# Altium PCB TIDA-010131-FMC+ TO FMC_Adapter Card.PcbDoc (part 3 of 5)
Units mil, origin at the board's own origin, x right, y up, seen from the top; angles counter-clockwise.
Board outline 2874.02 x 2362.2 mil, 12 copper layers (L1_Top Layer, L2_GND, L3_GND, L4_Signal layer1, L5_GND, L6_Signal Layer2, L7_GND, L8_Signal Layer3, L9_GND, L10_Signal Layer4, L11_GND, L12_Bottom Layer), stack 65.6 mil thick; 64 components, 219 nets, 2252 pads, 791 vias.
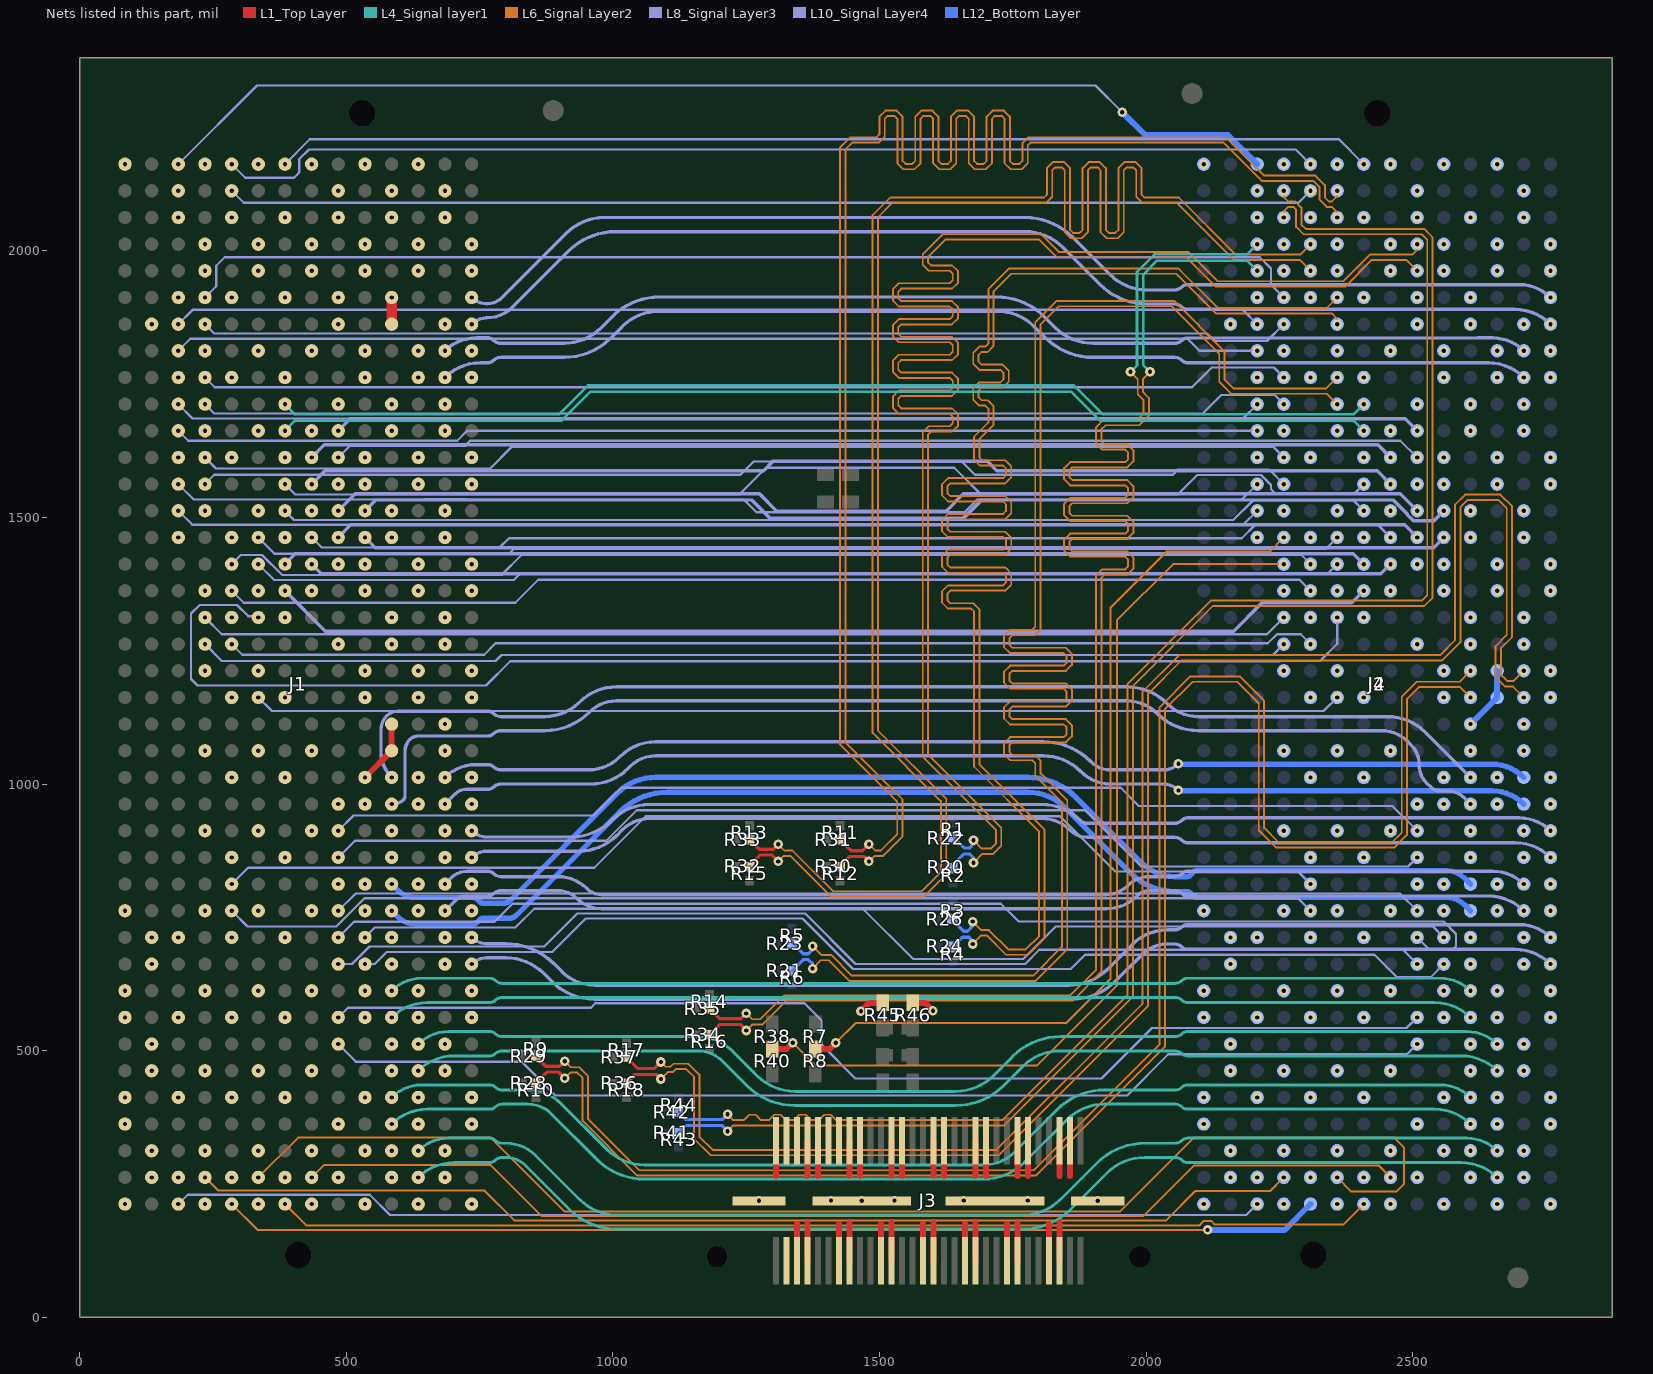
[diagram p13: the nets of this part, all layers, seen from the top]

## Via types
v1: diameter 18, hole 8, L1_Top Layer to L12_Bottom Layer, 791 vias

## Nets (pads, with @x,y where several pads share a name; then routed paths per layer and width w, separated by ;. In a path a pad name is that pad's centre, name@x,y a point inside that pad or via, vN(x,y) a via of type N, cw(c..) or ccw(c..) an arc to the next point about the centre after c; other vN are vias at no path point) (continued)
DAC_DA4_N: J1.A35 J2.A35 J4.A35 | length 2109.8
  L4_Signal layer1 w5.5: v1(635,462.5) cw(c702.36,395.14) 702.36,490.4 769.44,490.4 ccw(c769.44,504.06) 779.1,494.4 cw(c792.38,481.12) 792.38,499.9 1157.96,499.9 cw(c1157.96,431.96) 1206,480 1251.52,434.48 ccw(c1341.04,524) 1341.04,397.4 1642.7,397.4 ccw(c1642.7,524) 1732.22,434.48 1768.35,470.61 cw(c1839.06,399.9) 1839.06,499.9 2054.12,499.9 cw(c2054.12,481.12) 2067.4,494.4 ccw(c2077.06,504.06) 2077.06,490.4 2590.64,490.4 cw(c2590.64,395.14) v1(2658,462.5)
DAC_DA4_P: J1.A34 J2.A34 J4.A34 | length 2107.4
  L4_Signal layer1 w5.5: v1(635,512.5) cw(c691.73,455.77) 691.73,536 769.46,536 cw(c769.46,522.34) 779.11,532 ccw(c792.39,545.28) 792.39,526.5 1157.96,526.5 cw(c1157.96,431.96) 1224.81,498.81 1270.33,453.29 ccw(c1341.04,524) 1341.04,424 1642.7,424 ccw(c1642.7,524) 1713.41,453.29 1749.54,489.42 cw(c1839.06,399.9) 1839.06,526.5 2054.11,526.5 ccw(c2054.11,545.28) 2067.39,532 cw(c2077.04,522.34) 2077.04,536 2601.27,536 cw(c2601.27,455.77) v1(2658,512.5)
DAC_DA5_N: J1.A39 J2.A39 J4.A39 | length 2137
  L4_Signal layer1 w5.5: v1(635,262.5) cw(c702.36,195.14) 702.36,290.4 769.44,290.4 ccw(c769.44,304.06) 779.1,294.4 cw(c792.38,281.12) 792.38,299.9 800,299.9 cw(c800,248.96) 836.02,284.98 918.52,202.48 ccw(c1008.04,292) 1008.04,165.4 1768.58,165.4 ccw(c1768.58,292) 1858.1,202.48 1926.23,270.61 cw(c1996.94,199.9) 1996.94,299.9 2054.12,299.9 cw(c2054.12,281.12) 2067.4,294.4 ccw(c2077.06,304.06) 2077.06,290.4 2590.64,290.4 cw(c2590.64,195.14) v1(2658,262.5)
DAC_DA5_P: J1.A38 J2.A38 J4.A38 | length 2134.7
  L4_Signal layer1 w5.5: v1(635,312.5) cw(c691.73,255.77) 691.73,336 769.46,336 cw(c769.46,322.34) 779.11,332 ccw(c792.39,345.28) 792.39,326.5 800,326.5 cw(c800,248.96) 854.83,303.79 937.33,221.29 ccw(c1008.04,292) 1008.04,192 1768.58,192 ccw(c1768.58,292) 1839.29,221.29 1907.42,289.42 cw(c1996.94,199.9) 1996.94,326.5 2054.11,326.5 ccw(c2054.11,345.28) 2067.39,332 cw(c2077.04,322.34) 2077.04,336 2601.27,336 cw(c2601.27,255.77) v1(2658,312.5)
DAC_DA6_N: J1.B37 J2.B37 J4.B37 | length 2142.3
  L4_Signal layer1 w5.5: v1(585,362.5) cw(c652.36,295.14) 652.36,390.4 769.44,390.4 ccw(c769.44,404.06) 779.1,394.4 cw(c792.38,381.12) 792.38,399.9 840.79,399.9 cw(c840.79,338.79) 884,382 969.52,296.48 ccw(c1059.04,386) 969.58,296.42 ccw(c1059.04,386) 1059.04,259.4 1695.06,259.4 ccw(c1695.06,367.94) 1771.81,291.19 1851.23,370.61 cw(c1921.94,299.9) 1921.94,399.9 2054.12,399.9 cw(c2054.12,381.12) 2067.4,394.4 ccw(c2077.06,404.06) 2077.06,390.4 2540.64,390.4 cw(c2540.64,295.14) v1(2608,362.5)
DAC_DA6_P: J1.B36 J2.B36 J4.B36 | length 2142.5
  L4_Signal layer1 w5.5: v1(585,412.5) cw(c641.73,355.77) 641.73,436 769.46,436 cw(c769.46,422.34) 779.11,432 ccw(c792.39,445.28) 792.39,426.5 840.79,426.5 cw(c840.79,338.79) 902.81,400.81 988.33,315.29 ccw(c1059.04,386) 1059.04,286 1695.06,286 ; 1697.56,286 1695.06,286 ; v1(2608,412.5) ccw(c2551.27,355.77) 2551.27,436 2077.04,436 ccw(c2077.04,422.34) 2067.39,432 cw(c2054.11,445.28) 2054.11,426.5 1921.94,426.5 ccw(c1921.94,299.9) 1832.42,389.42 1753,310 cw(c1695.06,367.94) 1695.06,286
DAC_DA7_N: J1.B33 J2.B33 J4.B33 | length 2043
  L4_Signal layer1 w5.5: v1(585,562.5) cw(c652.36,495.14) 652.36,590.4 769.44,590.4 ccw(c769.44,604.06) 779.1,594.4 cw(c792.38,581.12) 792.38,599.9 2054.12,599.9 cw(c2054.12,581.12) 2067.4,594.4 ccw(c2077.06,604.06) 2077.06,590.4 2540.64,590.4 cw(c2540.64,495.14) v1(2608,562.5)
DAC_DA7_P: J1.B32 J2.B32 J4.B32 | length 2040.6
  L4_Signal layer1 w5.5: v1(585,612.5) cw(c641.73,555.77) 641.73,636 769.46,636 cw(c769.46,622.34) 779.11,632 ccw(c792.39,645.28) 792.39,626.5 2054.11,626.5 ccw(c2054.11,645.28) 2067.39,632 cw(c2077.04,622.34) 2077.04,636 2551.27,636 cw(c2551.27,555.77) v1(2608,612.5)
DAC_DB0_N: J1.B25 J2.B25 J4.B25 | length 2235.5
  L10_Signal Layer4 w6.3: v1(585,962.5) 587.3,962.5 ccw(c587.3,990.5) 607.1,970.7 ccw(c599.86,977.94) 610.1,977.94 610.1,1061.97 cw(c640.83,1061.97) 619.1,1083.7 cw(c634.79,1068.01) 634.79,1090.2 765.94,1090.2 ccw(c765.94,1103.86) 775.6,1094.2 cw(c790.09,1079.71) 790.09,1100.2 871.98,1100.2 ccw(c871.98,1219.02) 956,1135 cw(c1006.7,1084.3) 1006.7,1156 1963.06,1156 cw(c1963.06,1074.06) 2021,1132 ccw(c2097.77,1208.77) 2097.77,1100.2 2441.2,1100.2 cw(c2441.2,1029.95) 2486.14,1083.95 2496.32,1073.76 cw(c2458.96,1036.4) 2511.8,1036.4 ccw(c2561.29,1036.4) 2526.3,1001.4 2533.1,994.6 ccw(c2550.48,1011.98) 2550.48,987.4 2552.3,987.4 2552.3,987.1 2566.19,987.1 cw(c2566.19,945.56) 2595.57,974.93 v1(2608,962.5)
DAC_DB0_P: J1.B24 J2.B24 J4.B24 | length 2233.5
  L10_Signal Layer4 w6.3: v1(585,1012.5) cw(c633.28,1060.78) 565,1060.78 565,1101.44 cw(c602.56,1101.44) 576,1128 cw(c596.76,1107.24) 596.76,1136.6 765.96,1136.6 cw(c765.96,1122.94) 775.61,1132.6 ccw(c790.1,1147.09) 790.1,1126.6 871.98,1126.6 ccw(c871.98,1219.02) 937.33,1153.67 cw(c1006.7,1084.3) 1006.7,1182.4 1963.06,1182.4 cw(c1963.06,1074.06) 2039.67,1150.67 ccw(c2097.77,1208.77) 2097.77,1126.6 2452.48,1126.6 cw(c2452.48,1026.6) 2523.19,1097.31 v1(2608,1012.5)
DAC_DB1_N: J1.B29 J2.B29 J4.B29 | length 2206.4
  L12_Bottom Layer w10: v1(585,762.5) 596.53,750.97 ccw(c629.05,783.49) 629.05,737.5 738,737.5 ccw(c738,747.49) 745.07,740.43 750.21,745.57 cw(c757.28,738.51) 757.28,748.5 805.6,748.5 ccw(c805.6,767.58) 819.08,754.08 934,869 1012.21,947.21 cw(c1102.72,856.7) 1102.72,984.7 1777.78,984.7 cw(c1777.78,884.7) 1848.49,955.41 1970.83,833.08 ccw(c2054.3,916.55) 2054.3,798.5 2075.72,798.5 cw(c2075.72,788.51) 2082.79,795.57 2087.93,790.43 ccw(c2095,797.49) 2095,787.5 2563.95,787.5 cw(c2563.95,741.51) 2596.47,774.03 J2.B29@2608,762.5
DAC_DB1_P: J1.B28 J2.B28 J4.B28 | length 2207.6
  L12_Bottom Layer w10: v1(585,812.5) 596.53,800.97 ccw(c629.05,833.49) 629.05,787.5 738,787.5 cw(c738,777.51) 745.07,784.57 750.21,779.43 ccw(c757.28,786.49) 757.28,776.5 794,776.5 ccw(c794,795.58) 807.49,782.09 1008.81,983.41 cw(c1079.52,912.7) 1079.52,1012.7 1777.78,1012.7 cw(c1777.78,884.7) 1868.29,975.21 1990.63,852.88 ccw(c2054.3,916.55) 2054.3,826.5 2075.72,826.5 ccw(c2075.72,836.49) 2082.79,829.43 2087.93,834.57 cw(c2095,827.51) 2095,837.5 2563.95,837.5 cw(c2563.95,791.51) 2596.47,824.03 J2.B28@2608,812.5
DAC_DB2_N: J1.Y7 J4.Y7 | length 2141.4
  L10_Signal Layer4 w6.3: v1(735,1862.5) cw(c763.49,1834.01) 763.49,1874.3 ccw(c763.49,1941.44) 810.97,1893.97 915.98,1998.98 cw(c1005.36,1909.6) 1005.36,2036 1772.58,2036 cw(c1772.58,1936) 1843.29,2006.71 1912.78,1937.22 ccw(c2002.16,2026.6) 2002.16,1900.2 2052.91,1900.2 cw(c2052.91,1879.71) 2067.4,1894.2 ccw(c2077.06,1903.86) 2077.06,1890.2 2691.13,1890.2 cw(c2691.13,1795.63) v1(2758,1862.5)
DAC_DB2_P: J1.Y6 J4.Y6 | length 2142.7
  L10_Signal Layer4 w6.3: v1(735,1912.5) ccw(c763.49,1940.99) 763.49,1900.7 ccw(c763.49,1941.44) 792.3,1912.63 912.78,2033.11 cw(c983.49,1962.4) 983.49,2062.4 1772.58,2062.4 cw(c1772.58,1936) 1861.96,2025.38 1931.45,1955.89 ccw(c2002.16,2026.6) 2002.16,1926.6 2052.9,1926.6 ccw(c2052.9,1947.09) 2067.39,1932.6 cw(c2077.04,1922.94) 2077.04,1936.6 2699.82,1936.6 cw(c2699.82,1854.32) v1(2758,1912.5)
DAC_DB3_N: J1.Y27 J4.Y27 | length 2063.6
  L10_Signal Layer4 w6.3: v1(735,862.5) cw(c763.49,834.01) 763.49,874.3 936.21,874.3 ccw(c936.21,974.3) 1006.92,903.59 1017.67,914.33 cw(c1068.53,863.47) 1068.53,935.4 1804.39,935.4 cw(c1804.39,860.29) 1857.5,913.4 ccw(c1889.37,945.27) 1889.37,900.2 2052.91,900.2 cw(c2052.91,879.71) 2067.4,894.2 ccw(c2077.06,903.86) 2077.06,890.2 2691.13,890.2 cw(c2691.13,795.63) v1(2758,862.5)
DAC_DB3_P: J1.Y26 J4.Y26 | length 2061
  L10_Signal Layer4 w6.3: v1(735,912.5) ccw(c763.49,940.99) 763.49,900.7 921.02,900.7 ccw(c921.02,1010.98) 999,933 cw(c1068.53,863.47) 1068.53,961.8 1804.39,961.8 cw(c1804.39,860.29) 1876.17,932.07 ccw(c1889.37,945.27) 1889.37,926.6 2052.9,926.6 ccw(c2052.9,947.09) 2067.38,932.6 cw(c2077.04,922.94) 2077.04,936.6 2699.82,936.6 cw(c2699.82,854.32) v1(2758,912.5)
DAC_DB4_N: J1.Y31 J4.Y31 | length 2094.3
  L10_Signal Layer4 w6.3: v1(735,662.5) cw(c763.49,634.01) 763.49,674.3 799.28,674.3 cw(c799.28,574.3) 869.99,645.01 885,630 ccw(c965.63,710.63) 965.63,596.6 1860.73,596.6 ccw(c1860.73,711.44) 1941.94,630.24 1992.17,680.47 cw(c2039.8,632.84) 2039.8,700.2 2052.91,700.2 cw(c2052.91,679.71) 2067.4,694.2 ccw(c2077.06,703.86) 2077.06,690.2 2691.13,690.2 cw(c2691.13,595.63) v1(2758,662.5)
DAC_DB4_P: J1.Y30 J4.Y30 | length 2092.8
  L10_Signal Layer4 w6.3: v1(735,712.5) ccw(c763.49,740.99) 763.49,700.7 799.28,700.7 cw(c799.28,574.3) 888.66,663.68 903.67,648.67 ccw(c965.63,710.63) 965.63,623 1855.94,623 ccw(c1855.94,723) 1926.65,652.29 1973.5,699.14 cw(c2039.8,632.84) 2039.8,726.6 2052.9,726.6 ccw(c2052.9,747.09) 2067.38,732.6 cw(c2077.04,722.94) 2077.04,736.6 2699.82,736.6 cw(c2699.82,654.32) v1(2758,712.5)
DAC_DB5_N: J1.Z9 J4.Z9 | length 2095.7
  L10_Signal Layer4 w6.3: 753.1,1790.2 765.94,1790.2 ccw(c765.94,1803.86) 775.6,1794.2 cw(c790.09,1779.71) 790.09,1800.2 908.44,1800.2 ccw(c908.44,1923.56) 995.67,1836.33 1017.05,1857.71 cw(c1087.76,1787) 1087.76,1887 1719.58,1887 cw(c1719.58,1787) 1790.29,1857.71 1810.78,1837.22 ccw(c1900.16,1926.6) 1900.16,1800.2 2052.91,1800.2 cw(c2052.91,1779.71) 2067.4,1794.2 ccw(c2077.06,1803.86) 2077.06,1790.2 2637.9,1790.2
  L10_Signal Layer4 w6.5: v1(685,1762.5) cw(c751.87,1695.63) 751.87,1790.2 753.1,1790.2 ; 2637.9,1790.2 2641.13,1790.2 cw(c2641.13,1695.63) v1(2708,1762.5)
DAC_DB5_P: J1.Z8 J4.Z8 | length 2093.8
  L10_Signal Layer4 w6.3: 765.96,1836.6 cw(c765.96,1822.94) 775.61,1832.6 ccw(c790.1,1847.09) 790.1,1826.6 908.44,1826.6 ccw(c908.44,1923.56) 977,1855 998.38,1876.38 cw(c1087.76,1787) 1087.76,1913.4 1719.58,1913.4 cw(c1719.58,1787) 1808.96,1876.38 1829.45,1855.89 ccw(c1900.16,1926.6) 1900.16,1826.6 2052.9,1826.6 ccw(c2052.9,1847.09) 2067.38,1832.6 cw(c2077.04,1822.94) 2077.04,1836.6 2621.5,1836.6
  L10_Signal Layer4 w6.5: v1(685,1812.5) cw(c743.18,1754.32) 743.18,1836.6 765.96,1836.6 ; 2621.5,1836.6 2649.82,1836.6 cw(c2649.82,1754.32) v1(2708,1812.5)
DAC_DB6_N: J1.Z25 J4.Z25 | length 2074.9
  L10_Signal Layer4 w6.3: v1(685,962.5) 704.07,981.57 cw(c724.9,960.75) 724.9,990.2 765.94,990.2 ccw(c765.94,1003.86) 775.6,994.2 cw(c790.09,979.71) 790.09,1000.2 958.11,1000.2 ccw(c958.11,1100.2) 1028.82,1029.49 1032.67,1033.33 cw(c1080.15,985.85) 1080.15,1053 1806.58,1053 cw(c1806.58,953) 1877.29,1023.71 1878,1023 ccw(c1933.04,1078.04) 1933.04,1000.2 2031.33,1000.2 cw(c2031.33,959.23) v1(2060.3,988.2)
  L12_Bottom Layer w10: v1(2060.3,988.2) ccw(c2061.99,989.89) 2061.99,987.5 2647.64,987.5 cw(c2647.64,902.14) J4.Z25@2708,962.5
DAC_DB6_P: J1.Z24 J4.Z24 | length 2070.4
  L10_Signal Layer4 w6.3: v1(685,1012.5) cw(c743.18,954.32) 743.18,1036.6 765.96,1036.6 cw(c765.96,1022.94) 775.61,1032.6 ccw(c790.1,1047.09) 790.1,1026.6 952.68,1026.6 ccw(c952.68,1113.32) 1014,1052 cw(c1080.15,985.85) 1080.15,1079.4 1806.58,1079.4 cw(c1806.58,953) 1895.96,1042.38 1896.67,1041.67 ccw(c1933.04,1078.04) 1933.04,1026.6 2032.29,1026.6 ccw(c2032.29,1066.21) v1(2060.3,1038.2)
  L12_Bottom Layer w10: v1(2060.3,1038.2) ccw(c2061.99,1039.89) 2061.99,1037.5 2647.64,1037.5 cw(c2647.64,952.14) J4.Z24@2708,1012.5
DAC_DB7_N: J1.Z29 J4.Z29 | length 2064.2
  L10_Signal Layer4 w6.3: v1(685,762.5) 704.07,781.57 cw(c724.9,760.75) 724.9,790.2 765.94,790.2 ccw(c765.94,803.86) 775.6,794.2 cw(c790.09,779.71) 790.09,800.2 897.12,800.2 cw(c897.12,750.87) 932,785.75 ccw(c979.28,833.03) 979.28,766.17 1924.92,766.17 ccw(c1924.92,847.88) 1982.7,790.1 cw(c2007.08,765.72) 2007.08,800.2 2052.91,800.2 cw(c2052.91,779.71) 2067.4,794.2 ccw(c2077.06,803.86) 2077.06,790.2 2641.13,790.2 cw(c2641.13,695.63) v1(2708,762.5)
DAC_DB7_P: J1.Z28 J4.Z28 | length 2061.1
  L10_Signal Layer4 w6.3: v1(685,812.5) 696.75,824.25 cw(c726.56,794.44) 726.56,836.6 765.96,836.6 cw(c765.96,822.94) 775.61,832.6 ccw(c790.1,847.09) 790.1,826.6 897.12,826.6 cw(c897.12,750.87) 950.67,804.42 ccw(c979.28,833.03) 979.28,792.57 1924.92,792.57 ccw(c1924.92,847.88) 1964.03,808.77 cw(c2007.08,765.72) 2007.08,826.6 2052.9,826.6 ccw(c2052.9,847.09) 2067.38,832.6 cw(c2077.04,822.94) 2077.04,836.6 2649.82,836.6 cw(c2649.82,754.32) v1(2708,812.5)
DAC_SYNC_N: J1.F11 J2.F11 J4.F11 | length 2083.8
  L4_Signal layer1 w4.9: v1(385,1662.5) 404,1681.5 903.47,1681.5 957.83,1735.86 1859.14,1735.86 1913.5,1681.5 2389,1681.5 v1(2408,1662.5)
DAC_SYNC_P: J1.F10 J2.F10 J4.F10 | length 2083.8
  L4_Signal layer1 w4.9: v1(385,1712.5) 404,1693.5 898.5,1693.5 952.86,1747.86 1864.11,1747.86 1918.47,1693.5 2389,1693.5 v1(2408,1712.5)
DCLKOUT12_N: J4.Z21 R18.1 R36.2 | length 3204.2
  L1_Top Layer w6: R36.2@1025.25,438.96 1041.97,455.69 1081.32,455.69 v1(1090.01,447)
  L6_Signal Layer2 w3.5: v1(1090.01,447) 1103.01,460 1112,460 1117.68,465.68 1137.32,465.68 1152,451 1152,335 1183,304 1723.14,304 2003,583.86 2003,1168.86 2066.14,1232 2555.14,1232 2589,1265.86 2589,1518.86 2603.14,1533 2660,1533 2676,1517 2676,1280 2655,1259 2655,1201 2669.78,1186.22 2673,1183 2687.5,1183 v1(2708,1162.5)
DCLKOUT12_P: J4.Z20 R17.1 R37.2 | length 3206.1
  L1_Top Layer w6: R37.2@1025.25,487.96 1046.53,466.69 1077.69,466.69 v1(1090,479)
  L6_Signal Layer2 w3.5: v1(1090,479) 1099,470 1107.86,470 1113.54,475.68 1141.46,475.68 1162,455.14 1162,339.14 1187.14,314 1719,314 1993,588 1993,1173 2062,1242 2551,1242 2579,1270 2579,1524 2598,1543 2664.14,1543 2686,1521.14 2686,1275.86 2665,1254.86 2665,1205.14 2673.92,1196.22 2677.14,1193 2688.5,1193 v1(2708,1212.5)
E39: J1.E39 J2.E39 J4.E39 | length 2121
  L6_Signal Layer2 w3.75: v1(435,262.5) 458.5,286 770,286 865.75,190.25 1995.25,190.25 2090,285 2435.5,285 v1(2458,262.5)
F1: J1.F1 J2.F1 J4.F1 | length 2061.5
  L8_Signal Layer3 w4.25: v1(385,2162.5) 431.5,2209 2361.5,2209 v1(2408,2162.5)
F40: J1.F40 J2.F40 J4.F40 | length 2061.6
  L6_Signal Layer2 w3.75: v1(385,212.5) 424.75,172.75 2099.89,172.75 2108.01,180.88 2121.99,180.88 2128.86,174 2369.5,174 v1(2408,212.5)
F_LMX1_SDO: J3.55
FMC_DAC_SCLK: J1.C14 J2.C14 J4.C14 | length 2084
  L10_Signal Layer4 w6.5: v1(535,1512.5) 555.25,1532.75 647.32,1532.75 647.57,1533 722.43,1533 722.68,1532.75 747.32,1532.75 1260.25,1532.75 1294,1499 1657.25,1499 1691,1532.75 2463.56,1532.75 2489.75,1506.56 2489.75,1504.94 2500.44,1494.25 2539.75,1494.25 v1(2558,1512.5)
FMC_DAC_SDENB: J1.D15 J2.D15 J4.D15 | length 2042.5
  L10_Signal Layer4 w6.5: v1(485,1462.5) 508.5,1486 2484.5,1486 v1(2508,1462.5)
FMC_DAC_SDIO: J1.C15 J2.C15 J4.C15 | length 2038.7
  L10_Signal Layer4 w6.5: v1(535,1462.5) 554,1443.5 2539,1443.5 v1(2558,1462.5)
FMC_DAC_SDO: J1.D14 J2.D14 J4.D14 | length 2076.2
  L10_Signal Layer4 w6.5: v1(485,1512.5) 516.75,1544.25 642.56,1544.25 642.81,1544.5 727.19,1544.5 727.44,1544.25 742.56,1544.25 1274.75,1544.25 1307,1512 1624.75,1512 1657,1544.25 2476.25,1544.25 v1(2508,1512.5)
FMC_FSPICLKA: J1.J6 J2.J6 J4.J6 | length 2126
  L8_Signal Layer3 w4.25: v1(235,1912.5) 256,1933.5 256,1972 272,1988 2213,1988 2234,1967 2234,1936.5 v1(2258,1912.5)
FMC_FSPICLKB: J1.J7 J2.J7 J4.J7 | length 2049.1
  L8_Signal Layer3 w4.25: v1(235,1862.5) 252.5,1845 2114,1845 2128,1831 2226.5,1831 v1(2258,1862.5)
FMC_FSPICLKC: J1.J9 J2.J9 J4.J9 | length 2053.7
  L8_Signal Layer3 w4.25: v1(235,1762.5) 253.5,1744 2086,1744 2123,1781 2239.5,1781 v1(2258,1762.5)
FMC_FSPICLKD: J1.J10 J2.J10 J4.J10 | length 2051.7
  L8_Signal Layer3 w4.25: v1(235,1712.5) 252.5,1695 2106,1695 2140.63,1729.63 2240.88,1729.63 v1(2258,1712.5)
FMC_FSPIDA: J1.J12 J2.J12 J4.J12 | length 2056.1
  L8_Signal Layer3 w4.25: v1(235,1612.5) 255.5,1592 770,1592 810,1632 2238.5,1632 v1(2258,1612.5)
FMC_FSPIDB: J1.J13 J2.J13 J4.J13 | length 2065.9
  L8_Signal Layer3 w4.25: v1(235,1562.5) 252.5,1580 1239,1580 1264,1605 1654,1605 1679,1580 2050,1580 2059.25,1589.25 2231.25,1589.25 v1(2258,1562.5)
FMC_LMK_CS: J1.H17 J2.H17 J4.H17 | length 2058.6
  L8_Signal Layer3 w4.25: v1(285,1362.5) 307.5,1340 817,1340 860,1383 2287.5,1383 v1(2308,1362.5)
FMC_LMK_SCK: J1.G15 J2.G15 J4.G15 | length 2048.3
  L8_Signal Layer3 w4.25: v1(335,1462.5) 365.5,1432 805,1432 814,1441 2336.5,1441 v1(2358,1462.5)
FMC_LMK_SDIO: J1.G16 J2.G16 J4.G16 | length 2047.6
  L8_Signal Layer3 w4.25: v1(335,1412.5) 364.75,1382.75 814,1382.75 826.25,1395 2340.5,1395 v1(2358,1412.5)
FMC_LMK_SDO: J1.H16 J2.H16 J4.H16 | length 2068.7
  L8_Signal Layer3 w4.25: v1(285,1412.5) 302.12,1429.62 342.09,1429.62 379.72,1392 791,1392 829,1430 2290.5,1430 v1(2308,1412.5)
FMC_RXADSA1PD: J1.K7 J2.K7 J4.K7 | length 2045.2
  L8_Signal Layer3 w4.25: v1(185,1862.5) 211.75,1889.25 2181.25,1889.25 v1(2208,1862.5)
FMC_RXADSA2PD: J1.K8 J2.K8 J4.K8 | length 2041.6
  L8_Signal Layer3 w4.25: v1(185,1812.5) 207.5,1835 2077.5,1835 2100,1812.5 v1(2208,1812.5)
FMC_RXADSAFAST: J1.G18 J2.G18 J4.G18 | length 2501.1
  L8_Signal Layer3 w4.25: v1(335,1312.5) 332.5,1315 316,1315 295,1336 225,1336 209,1320 209,1197 221,1185 762,1185 807.5,1230.5 2250.19,1230.5 2250.44,1230.75 2325.75,1230.75 2358,1263 v1(2358,1312.5)
FMC_RXAPD2H: J1.K10 J2.K10 J4.K10 | length 2045.2
  L8_Signal Layer3 w4.25: v1(185,1712.5) 211.75,1685.75 2181.25,1685.75 v1(2208,1712.5)
FMC_RXAPD2L: J1.K11 J2.K11 J4.K11 | length 2038.3
  L8_Signal Layer3 w4.25: v1(185,1662.5) 203.5,1644 708,1644 726.5,1662.5 v1(2208,1662.5)
FMC_RXBDSA1PD: J1.K13 J2.K13 J4.K13 | length 2066.5
  L8_Signal Layer3 w4.25: v1(185,1562.5) 213.75,1533.75 1245.25,1533.75 1269,1510 1659.25,1510 1683,1533.75 2179.25,1533.75 v1(2208,1562.5)
FMC_RXBDSA2PD: J1.K14 J2.K14 J4.K14 | length 2044.8
  L8_Signal Layer3 w4.25: v1(185,1512.5) 211.38,1486.12 2181.62,1486.12 v1(2208,1512.5)
FMC_RXBDSAFAST: J1.G21 J2.G21 J4.G21 | length 2044.1
  L8_Signal Layer3 w4.25: v1(335,1162.5) 360.5,1137 2332.5,1137 v1(2358,1162.5)
FMC_RXBPD2H: J1.J18 J2.J18 J4.J18 | length 2049.1
  L8_Signal Layer3 w4.25: v1(235,1312.5) 266.5,1281 2226.5,1281 v1(2258,1312.5)
FMC_RXBPD2L: J1.J19 J2.J19 J4.J19 | length 2049.1
  L8_Signal Layer3 w4.25: v1(235,1262.5) 266.5,1231 780,1231 791,1242 2237.5,1242 v1(2258,1262.5)
FMC_RXDSASW: J1.F13 J2.F13 J4.F13 | length 2114.6
  L8_Signal Layer3 w4.25: v1(385,1562.5) 404.5,1543 1237,1543 1287,1593 1640,1593 1690,1543 2059,1543 2095.63,1579.63 2215.09,1579.63 2234.06,1560.66 2234.06,1552.94 2243,1544 2389.5,1544 v1(2408,1562.5)
FMC_SCL: J1.C30 J2.C30 J4.C30 | length 2118.3
  L8_Signal Layer3 w4.25: v1(535,712.5) 553.5,731 817,731 852.5,766.5 1468.5,766.5 1563,672 1769.24,672 1830.24,733 2537.5,733 v1(2558,712.5)
FMC_SDA: J1.C31 J2.C31 J4.C31 | length 2136.1
  L8_Signal Layer3 w4.25: v1(535,662.5) 553.5,662.5 576,685 886,685 949,748 1355.5,748 1450,653.5 1858.5,653.5 1885,680 2428,680 2470,638 2533.5,638 v1(2558,662.5)
FMC_SPI_CLK1: J3.57
FMC_SPI_SCSB1: J3.47
FMC_SPI_SCSB2: J3.58
FMC_SPI_SDIO1: J3.49
FMC_SPIACLK: J1.D11 J2.D11 J4.D11 | length 2041.6
  L10_Signal Layer4 w6.5: v1(485,1662.5) 507.5,1685 2485.5,1685 v1(2508,1662.5)
FMC_SPIASDIO: J1.D12 J2.D12 J4.D12 | length 2049.1
  L8_Signal Layer3 w4.25: v1(485,1612.5) 506.5,1634 722,1634 732,1644 2476.5,1644 v1(2508,1612.5)
FMC_SPIASDO: J1.D26 J2.D26 J4.D26 | length 2089.7
  L8_Signal Layer3 w4.25: v1(485,912.5) 513.5,941 963,941 1015,993 1952,993 1986,959 2461.5,959 v1(2508,912.5)
FMC_SPIASEN: J1.D27 J2.D27 J4.D27 | length 2110.5
  L8_Signal Layer3 w4.25: v1(485,862.5) 516.5,894 987.4,894 1044.4,951 1885,951 1990.62,845.38 2490.87,845.38 v1(2508,862.5)
FMC_SPIBCLK: J1.E12 J2.E12 J4.E12 | length 2042.5
  L10_Signal Layer4 w6.5: v1(435,1612.5) 458.5,1636 2434.5,1636 v1(2458,1612.5)
FMC_SPIBSDIO: J1.E13 J2.E13 J4.E13 | length 2058.2
  L10_Signal Layer4 w6.5: v1(435,1562.5) 460,1587.5 1282.5,1587.5 1300,1605 1702.5,1605 1720,1587.5 2433,1587.5 v1(2458,1562.5)
FMC_SPIBSDO: J1.E15 J2.E15 J4.E15 | length 2059
  L8_Signal Layer3 w4.25: v1(435,1462.5) 454,1443.5 787.5,1443.5 805,1461 2179,1461 2205,1487 2433.5,1487 v1(2458,1462.5)
FMC_SPIBSEN: J1.E16 J2.E16 J4.E16 | length 2038.1
  L10_Signal Layer4 w6.5: v1(435,1412.5) 453.25,1394.25 2439.75,1394.25 v1(2458,1412.5)
FMC_TCK: J1.D29 J2.D29 J4.D29 | length 2049.9
  L8_Signal Layer3 w4.25: v1(485,762.5) 517.5,795 2475.5,795 v1(2508,762.5)
FMC_TDI: J1.D30 J2.D30 J4.D30 | length 2254.3
  L8_Signal Layer3 w4.25: v1(485,712.5) 514.5,742 778,742 811.75,775.75 1727.25,775.75 1760.75,742.25 2557.75,742.25 2581,719 2581,696 2574,689 2531.5,689 v1(2508,712.5)
FMC_TDO: J1.D31 J2.D31 J4.D31 | length 2123.4
  L8_Signal Layer3 w4.25: v1(485,662.5) 510.78,662.5 543.66,695.38 871.38,695.38 933.25,757.25 1360.5,757.25 1455,662.75 1773.07,662.75 1799.57,689.25 2481.25,689.25 v1(2508,662.5)
FMC_TMS: J1.D33 J2.D33 J4.D33 | length 2166.5
  L8_Signal Layer3 w4.25: v1(485,562.5) 503.25,580.75 958.75,580.75 967,589 1359,589 1391,557 1391,511.5 1454.5,448 1916.26,448 2010.76,542.5 2488,542.5 v1(2508,562.5)
FMC_TRSTB: J1.D34 J2.D34 J4.D34 | length 2102.7
  L8_Signal Layer3 w4.25: v1(485,512.5) 517.88,479.62 828.38,479.62 891.75,416.25 1964.25,416.25 2041.5,493.5 2489,493.5 v1(2508,512.5)
FMC_TXDSASW: J1.F14 J2.F14 J4.F14 | length 2053.3
  L8_Signal Layer3 w4.25: v1(385,1512.5) 402.13,1495.37 2163.37,1495.37 2200,1532 2388.5,1532 v1(2408,1512.5)
FMC_TXTDD1: J1.F16 J2.F16 J4.F16 | length 2039.2
  L10_Signal Layer4 w6.5: v1(385,1412.5) 404.5,1432 2388.5,1432 v1(2408,1412.5)
FMC_TXTDD2: J1.F17 J2.F17 J4.F17 | length 2085.5
  L10_Signal Layer4 w6.5: v1(385,1362.5) 460.5,1287 2164,1287 2217,1340 2385.5,1340 v1(2408,1362.5)
FPGA_CLK1_N: J2.K5 J4.K5 R16.1 R34.2 | length 3184
  L1_Top Layer w6: R34.2@1181.01,529 R34.2@1181.5,529.5 ; R34.2@1181,530 1200,549 1240,549 1250.01,538.99 v1(1250.01,538)
  L6_Signal Layer2 w3.5: v1(1250.01,538) 1261.01,549 1280,549 1325,594 1862,594 1916,648 1916,1387.3 1921.45,1392.75 1964.7,1392.75 1976,1404.05 1976,1424.95 1964.7,1436.25 1861.45,1436.25 1856,1441.7 1856,1454.3 1861.45,1459.75 1964.7,1459.75 1976,1471.05 1976,1491.95 1964.7,1503.25 1861.45,1503.25 1856,1508.7 1856,1521.3 1861.45,1526.75 1964.7,1526.75 1976,1538.05 1976,1558.95 1964.7,1570.25 1861.45,1570.25 1856,1575.7 1856,1588.3 1861.45,1593.75 1964.7,1593.75 1976,1605.05 1976,1625.95 1964.7,1637.25 1921.45,1637.25 1916,1642.7 1916,1665 1924,1673 1987,1673 2005,1691 2005,1724 1994.2,1734.8 1994.2,1760.2 v1(2007,1773)
  L4_Signal layer1 w4.9: v1(2007,1773) 1994.7,1785.3 1994.7,1955.7 2020.5,1981.5 2189,1981.5 v1(2208,1962.5)
FPGA_CLK1_P: J2.K4 J4.K4 R14.1 R35.2 | length 3186
  L1_Top Layer w6: R35.2@1181,579 1200,560 1240,560 v1(1250,570)
  L6_Signal Layer2 w3.5: v1(1250,570) 1261,559 1275.86,559 1320.86,604 1857.86,604 1906,652.14 1906,1391.45 1917.3,1402.75 1960.55,1402.75 1966,1408.2 1966,1420.8 1960.55,1426.25 1857.3,1426.25 1846,1437.55 1846,1458.45 1857.3,1469.75 1960.55,1469.75 1966,1475.2 1966,1487.8 1960.55,1493.25 1857.3,1493.25 1846,1504.55 1846,1525.45 1857.3,1536.75 1960.55,1536.75 1966,1542.2 1966,1554.8 1960.55,1560.25 1857.3,1560.25 1846,1571.55 1846,1592.45 1857.3,1603.75 1960.55,1603.75 1966,1609.2 1966,1621.8 1960.55,1627.25 1917.3,1627.25 1906,1638.55 1906,1669.14 1919.86,1683 1982.86,1683 1995,1695.14 1995,1719.86 1984.2,1730.66 1984.2,1759.2 v1(1970.4,1773)
  L4_Signal layer1 w4.9: v1(1970.4,1773) 1982.7,1785.3 1982.7,1960.67 2015.53,1993.5 2189,1993.5 v1(2208,2012.5)
FPGA_CLK2_N: J2.J3 J4.J3 R42.2 R44.2 | length 3196.3
  L6_Signal Layer2 w3.5: v1(1215,381) 1226,370 1238,370 1245.63,370 1249.75,374.12 1255.62,380 1267.38,380 1273.25,374.12 1277.37,370 1292.63,370 1296.75,374.12 1302.62,380 1314.38,380 1320.25,374.12 1324.37,370 1339.63,370 1343.75,374.12 1349.62,380 1361.38,380 1367.25,374.12 1371.37,370 1386.63,370 1390.75,374.12 1396.62,380 1408.38,380 1414.25,374.12 1418.37,370 1424,370 1730,370 1965,605 1965,1188 2121,1344 2517,1344 2527,1354 2527,2020.86 2516.86,2031 2294.86,2031 2281,2044.86 2281,2077 2275.5,2082.5 2266,2082.5 2258,2074.5 v1(2258,2062.5)
  L12_Bottom Layer w6: R44.2@1122.98,385 1136.98,371 1205,371 v1(1215,381)
FPGA_CLK2_P: J2.J2 J4.J2 R41.2 R43.2 | length 3196.7
  L6_Signal Layer2 w3.5: v1(1215.01,349) 1226.01,360 1734.14,360 1975,600.86 1975,1183.86 2125.14,1334 2521.14,1334 2537,1349.86 2537,2025 2521,2041 2299,2041 2291,2049 2291,2081.14 2279.64,2092.5 2266,2092.5 2258,2100.5 v1(2258,2112.5)
  L12_Bottom Layer w6: R41.2@1122.98,346 1136.98,360 1204.01,360 v1(1215.01,349)
FPGA_JESD_CLK_A_N: J2.D5 J4.D5 R2.1 R20.1 | length 3192.4
  L6_Signal Layer2 w3.5: v1(1676.15,852.67) 1692.65,869.17 1712.76,869.17 1728,884.41 1728,918.14 1725.07,921.07 1591,1055.14 1591,1655.63 1596.45,1661.07 1635.77,1661.07 1647.07,1672.38 1647.07,1693.27 1635.77,1704.57 1540.37,1704.57 1534.93,1710.02 1534.93,1722.63 1540.37,1728.07 1635.77,1728.07 1647.07,1739.38 1647.07,1760.27 1635.77,1771.57 1540.37,1771.57 1534.93,1777.02 1534.93,1789.63 1540.37,1795.07 1635.77,1795.07 1647.07,1806.38 1647.07,1827.27 1635.77,1838.57 1540.37,1838.57 1534.93,1844.02 1534.93,1856.63 1540.37,1862.07 1635.77,1862.07 1647.07,1873.38 1647.07,1894.27 1635.77,1905.57 1540.37,1905.57 1534.93,1911.02 1534.93,1923.63 1540.37,1929.07 1635.77,1929.07 1647.07,1940.38 1647.07,1961.27 1635.77,1972.57 1596.45,1972.57 1591,1978.02 1591,1989 1623,2021 1799,2021 1832,1988 2075,1988 2130,1933 2373.14,1933 2423.14,1983 2487.5,1983 v1(2508,1962.5)
  L12_Bottom Layer w6: R2.1@1637.75,848.56 1658.18,869 1668.87,869 1676.12,861.75 v1@1676.12,852.67
FPGA_JESD_CLK_A_P: J2.D4 J4.D4 R1.1 R22.1 | length 3195.8
  L6_Signal Layer2 w3.5: v1(1676.15,894.67) 1691.65,879.17 1708.62,879.17 1718,888.56 1718,914 1581,1051 1581,1659.77 1592.3,1671.07 1631.63,1671.07 1637.07,1676.52 1637.07,1689.13 1631.63,1694.57 1536.23,1694.57 1524.93,1705.88 1524.93,1726.77 1536.23,1738.07 1631.63,1738.07 1637.07,1743.52 1637.07,1756.13 1631.63,1761.57 1536.23,1761.57 1524.93,1772.88 1524.93,1793.77 1536.23,1805.07 1631.63,1805.07 1637.07,1810.52 1637.07,1823.13 1631.63,1828.57 1536.23,1828.57 1524.93,1839.88 1524.93,1860.77 1536.23,1872.07 1631.63,1872.07 1637.07,1877.52 1637.07,1890.13 1631.63,1895.57 1536.23,1895.57 1524.93,1906.88 1524.93,1927.77 1536.23,1939.07 1631.63,1939.07 1637.07,1944.52 1637.07,1957.13 1631.63,1962.57 1592.3,1962.57 1581,1973.88 1581,1993.14 1615.93,2028.07 1618.86,2031 1803.14,2031 1806.07,2028.07 1836.14,1998 2079.14,1998 2101.14,1976 2134.14,1943 2369,1943 2419,1993 2499,1993 2508,2002 v1(2508,2012.5)
  L12_Bottom Layer w6: R1.1@1637.75,901.54 1659.28,880 1667.77,880 1676.12,888.35 v1@1676.12,894.67
FPGA_JESD_CLK_B_N: J2.G7 J4.G7 R4.2 R24.1 | length 3206.2
  L6_Signal Layer2 w3.5: v1(1674.59,700.24) 1690.59,716.24 1700.76,716.24 1737,680 1778.14,680 1809,710.86 1809,764.86 1809,915.14 1785,939.14 1687,1037.14 1687,1327.95 1675.7,1339.25 1632.45,1339.25 1627,1344.7 1627,1357.3 1632.45,1362.75 1735.7,1362.75 1747,1374.05 1747,1394.95 1735.7,1406.25 1632.45,1406.25 1627,1411.7 1627,1424.3 1632.45,1429.75 1735.7,1429.75 1747,1441.05 1747,1461.95 1735.7,1473.25 1632.45,1473.25 1627,1478.7 1627,1491.3 1632.45,1496.75 1735.7,1496.75 1747,1508.05 1747,1528.95 1735.7,1540.25 1632.45,1540.25 1627,1545.7 1627,1558.3 1632.45,1563.75 1735.7,1563.75 1747,1575.05 1747,1595.95 1735.7,1607.25 1692.45,1607.25 1687,1612.7 1687,1647 1713.93,1673.93 1713.93,1708.45 1702.62,1719.75 1691.12,1719.75 1685.67,1725.2 1685.67,1737.8 1691.12,1743.25 1730.88,1743.25 1742.18,1754.55 1742.18,1775.45 1730.88,1786.75 1691.12,1786.75 1685.67,1792.2 1685.67,1804.8 1691.12,1810.25 1702.62,1810.25 1713.93,1821.55 1713.93,1923.93 1746.93,1956.93 2056.07,1956.93 2130.5,1882.5 2347.5,1882.5 2358,1872 v1(2358,1862.5)
  L12_Bottom Layer w6: R4.2@1635.59,693.38 1655.21,713 1667.53,713 1673.96,706.57 v1@1673.96,697.49
FPGA_JESD_CLK_B_P: J2.G6 J4.G6 R3.2 R26.1 | length 3200.2
  L6_Signal Layer2 w3.5: v1(1674.59,742.24) 1690.59,726.24 1704.9,726.24 1741.14,690 1774,690 1799,715 1799,911 1677,1033 1677,1323.8 1671.55,1329.25 1628.3,1329.25 1617,1340.55 1617,1361.45 1628.3,1372.75 1731.55,1372.75 1737,1378.2 1737,1390.8 1731.55,1396.25 1628.3,1396.25 1617,1407.55 1617,1428.45 1628.3,1439.75 1731.55,1439.75 1737,1445.2 1737,1457.8 1731.55,1463.25 1628.3,1463.25 1617,1474.55 1617,1495.45 1628.3,1506.75 1731.55,1506.75 1737,1512.2 1737,1524.8 1731.55,1530.25 1628.3,1530.25 1617,1541.55 1617,1562.45 1628.3,1573.75 1731.55,1573.75 1737,1579.2 1737,1591.8 1731.55,1597.25 1688.3,1597.25 1677,1608.55 1677,1651.14 1703.93,1678.07 1703.93,1704.3 1698.48,1709.75 1686.98,1709.75 1675.67,1721.05 1675.67,1741.95 1686.98,1753.25 1726.74,1753.25 1732.18,1758.7 1732.18,1771.3 1726.74,1776.75 1686.98,1776.75 1675.67,1788.05 1675.67,1808.95 1686.98,1820.25 1698.48,1820.25 1703.93,1825.7 1703.93,1928.07 1742.79,1966.93 2060.21,1966.93 2063.14,1964 2134.64,1892.5 2338,1892.5 v1(2358,1912.5)
  L12_Bottom Layer w6: R26.1@1635.59,746.35 1657.94,724 1664.8,724 1673.96,733.16 v1@1673.96,739.49
FPGA_JESD_CLK_C_N: J2.G3 J4.G3 R12.2 R30.2 | length 3197.1
  L1_Top Layer w6: R30.2@1426,846.02 R30.2@1426.5,846.51 ; R30.2@1426,847.02 1442.98,864 1471.02,864 v1(1480.01,855.02)
  L6_Signal Layer2 w3.5: v1(1480.01,855.02) 1490.51,865.52 1506.56,865.52 1543,901.96 1543,971.14 1529,985.14 1436,1078.14 1436,2190 1449,2203 1498.45,2203 1509.75,2214.3 1509.75,2247.55 1515.2,2253 1527.8,2253 1533.25,2247.55 1533.25,2164.3 1544.55,2153 1565.45,2153 1576.75,2164.3 1576.75,2247.55 1582.2,2253 1594.8,2253 1600.25,2247.55 1600.25,2164.3 1611.55,2153 1632.45,2153 1643.75,2164.3 1643.75,2247.55 1649.2,2253 1661.8,2253 1667.25,2247.55 1667.25,2164.3 1678.55,2153 1699.45,2153 1710.75,2164.3 1710.75,2247.55 1716.2,2253 1728.8,2253 1734.25,2247.55 1734.25,2164.3 1745.55,2153 1766.45,2153 1777.75,2164.3 1777.75,2197.55 1783.2,2203 2145,2203 2217,2131 2313.19,2131 2325,2119.19 2325,2095.86 2338.36,2082.5 2348,2082.5 2358,2072.5 v1(2358,2062.5)
FPGA_JESD_CLK_C_P: J2.G2 J4.G2 R11.2 R31.2 | length 3199.7
  L1_Top Layer w6: R31.2@1426,896.02 1447.02,875 1467.98,875 v1(1480,887.02)
  L6_Signal Layer2 w3.5: v1(1480,887.02) 1491.5,875.52 1502.41,875.52 1533,906.1 1533,967 1426,1074 1426,2194.14 1444.86,2213 1494.3,2213 1499.75,2218.45 1499.75,2251.7 1511.05,2263 1531.95,2263 1543.25,2251.7 1543.25,2168.45 1548.7,2163 1561.3,2163 1566.75,2168.45 1566.75,2251.7 1578.05,2263 1598.95,2263 1610.25,2251.7 1610.25,2168.45 1615.7,2163 1628.3,2163 1633.75,2168.45 1633.75,2251.7 1645.05,2263 1665.95,2263 1677.25,2251.7 1677.25,2168.45 1682.7,2163 1695.3,2163 1700.75,2168.45 1700.75,2251.7 1712.05,2263 1732.95,2263 1744.25,2251.7 1744.25,2168.45 1749.7,2163 1762.3,2163 1767.75,2168.45 1767.75,2201.7 1779.05,2213 2149.14,2213 2221.14,2141 2317.33,2141 2335,2123.33 2335,2100 2342.5,2092.5 2348,2092.5 2358,2102.5 v1(2358,2112.5)
FPGA_JESD_CLK_D_N: J2.H5 J4.H5 R15.1 R32.2 | length 3201.5
  L1_Top Layer w6: R32.2@1255.99,847 1275.99,867 1298,867 v1(1310,855) ; R32.2@1255.99,846 R32.2@1256.5,846.5
  L6_Signal Layer2 w3.5: v1(1310,855) 1320.5,865.5 1332.41,865.5 1408.91,789 1583.14,789 1625,830.86 1625,972.14 1497,1100.14 1497,2063 1524,2090 1812.45,2090 1823.75,2101.3 1823.75,2150.94 1829.2,2156.39 1841.8,2156.39 1847.25,2150.94 1847.25,2034.92 1858.55,2023.61 1879.45,2023.61 1890.75,2034.92 1890.75,2150.94 1896.2,2156.39 1908.8,2156.39 1914.25,2150.94 1914.25,2034.92 1925.55,2023.61 1946.45,2023.61 1957.75,2034.92 1957.75,2150.94 1963.2,2156.39 1975.8,2156.39 1981.25,2150.94 1981.25,2101.3 1992.55,2090 2057,2090 2164,1983 2287.5,1983 v1(2308,1962.5)
FPGA_JESD_CLK_D_P: J2.H4 J4.H4 R13.1 R33.2 | length 3198.7
  L1_Top Layer w6: R33.2@1255.99,896 1273.99,878 1300.99,878 v1(1309.99,887)
  L6_Signal Layer2 w3.5: v1(1309.99,887) 1321.49,875.5 1336.56,875.5 1413.06,799 1579,799 1615,835 1615,968 1487,1096 1487,2067.14 1519.86,2100 1808.3,2100 1813.75,2105.45 1813.75,2155.08 1825.05,2166.39 1845.95,2166.39 1857.25,2155.08 1857.25,2039.06 1862.7,2033.61 1875.3,2033.61 1880.75,2039.06 1880.75,2155.08 1892.05,2166.39 1912.95,2166.39 1924.25,2155.08 1924.25,2039.06 1929.7,2033.61 1942.3,2033.61 1947.75,2039.06 1947.75,2155.08 1959.05,2166.39 1979.95,2166.39 1991.25,2155.08 1991.25,2105.45 1996.7,2100 2061.14,2100 2168.14,1993 2288.5,1993 v1(2308,2012.5)
FPGA_JESD_SYSREFM: J2.G10 J4.G10 R6.2 R21.1 | length 3196.8
  L6_Signal Layer2 w3.5: v1(1374.3,654.12) 1389.8,669.62 1404.82,669.62 1443.44,631 1792.56,631 1852,690.44 1852,970 1802,1020 1802,1043.45 1790.7,1054.75 1748.73,1054.75 1743.28,1060.2 1743.28,1072.8 1748.73,1078.25 1849.41,1078.25 1860.72,1089.55 1860.72,1110.45 1849.41,1121.75 1748.73,1121.75 1743.28,1127.2 1743.28,1139.8 1748.73,1145.25 1849.41,1145.25 1860.72,1156.55 1860.72,1177.45 1849.41,1188.75 1748.73,1188.75 1743.28,1194.2 1743.28,1206.8 1748.73,1212.25 1849.41,1212.25 1860.72,1223.55 1860.72,1244.45 1849.41,1255.75 1748.73,1255.75 1743.28,1261.2 1743.28,1273.8 1748.73,1279.25 1790.7,1279.25 1802,1290.55 1802,1862 1836,1896 2048,1896 2137,1807 2137,1754.44 2159.44,1732 2338.5,1732 v1(2358,1712.5)
  L12_Bottom Layer w6: R6.2@1335.93,650.01 1356.91,671 1366.5,671 1374.3,663.2 v1(1374.3,654.12)
FPGA_JESD_SYSREFP: J2.G9 J4.G9 R5.2 R23.1 | length 3194.9
  L6_Signal Layer2 w3.5: v1(1374.3,696.12) 1390.8,679.62 1408.96,679.62 1447.59,641 1788.41,641 1842,694.59 1842,965.86 1792,1015.86 1792,1039.3 1786.55,1044.75 1744.59,1044.75 1733.28,1056.05 1733.28,1076.95 1744.59,1088.25 1845.27,1088.25 1850.72,1093.7 1850.72,1106.3 1845.27,1111.75 1744.59,1111.75 1733.28,1123.05 1733.28,1143.95 1744.59,1155.25 1845.27,1155.25 1850.72,1160.7 1850.72,1173.3 1845.27,1178.75 1744.59,1178.75 1733.28,1190.05 1733.28,1210.95 1744.59,1222.25 1845.27,1222.25 1850.72,1227.7 1850.72,1240.3 1845.27,1245.75 1744.59,1245.75 1733.28,1257.05 1733.28,1277.95 1744.59,1289.25 1786.55,1289.25 1792,1294.7 1792,1866.14 1831.86,1906 2052.14,1906 2147,1811.14 2147,1758.59 2163.59,1742 2337.5,1742 v1(2358,1762.5)
  L12_Bottom Layer w6: R5.2@1335.93,702.99 1356.91,682 1366.5,682 1374.3,689.8 v1(1374.3,696.12)
G39: J1.G39 J2.G39 J4.G39 | length 2511.4
  L6_Signal Layer2 w3.75: v1(335,262.5) 409.5,337 771,337 909,199 1951,199 2089,337 2465,337 2483,319 2483,250 2469,236 2384.5,236 v1(2358,262.5)
GBTCLK1_M2C_N: J2.B21 J4.B21 R10.1 R28.2 | length 3201.5
  L1_Top Layer w6: R28.2@855.5,439.5 876,460 898,460 v1(909.5,448.5)
  L6_Signal Layer2 w3.5: v1(909.5,448.5) 920,459 933,459 943,449 943,368.44 1045.44,266 1793.14,266 2035,507.86 2035,1140 2087,1192 2171,1192 2211,1152 2211,999.86 2211,913.86 2243.86,881 2465,881 2486.07,902.07 2489,905 2489,1160 2511,1182 2588.5,1182 v1(2608,1162.5)
GBTCLK1_M2C_P: J2.B20 J4.B20 R9.1 R29.2 | length 3200.7
  L1_Top Layer w6: R29.2@855.49,489.5 873.99,471 899.99,471 v1(909.49,480.5)
  L6_Signal Layer2 w3.5: v1(909.49,480.5) 920.99,469 937.14,469 953,453.14 953,372.59 1049.59,276 1789,276 2025,512 2025,1144.14 2082.86,1202 2175.14,1202 2221,1156.14 2221,918 2248,891 2460.86,891 2479,909.14 2479,1164.14 2506.86,1192 2587.5,1192 v1(2608,1212.5)
GND: J1.A1 J1.A4 J1.A5 J1.A8 J1.A9 J1.A12 J1.A13 J1.A16 J1.A17 J1.A20 J1.A21 J1.A24 J1.A25 J1.A28 J1.A29 J1.A32 J1.A33 J1.A36 J1.A37 J1.A40 J1.B2 J1.B3 J1.B6 J1.B7 J1.B10 J1.B11 J1.B14 J1.B15 J1.B18 J1.B19 J1.B22 J1.B23 J1.B26 J1.B27 J1.B30 J1.B31 J1.B34 J1.B35 J1.B38 J1.B39 J1.C1 J1.C4 J1.C5 J1.C8 J1.C9 J1.C12 J1.C13 J1.C16 J1.C17 J1.C20 J1.C21 J1.C24 J1.C25 J1.C28 J1.C29 J1.C32 J1.C33 J1.C36 J1.C38 J1.C40 J1.D2 J1.D3 J1.D6 J1.D7 J1.D10 J1.D13 J1.D16 J1.D19 J1.D25 J1.D28 J1.D37 J1.D39 J1.E1 J1.E4 J1.E5 J1.E8 J1.E11 J1.E14 J1.E17 J1.E23 J1.E26 J1.E29 J1.E32 J1.E35 J1.E38 J1.E40 J1.F3 J1.F6 J1.F9 J1.F12 J1.F15 J1.F18 J1.F21 J1.F24 J1.F27 J1.F30 J1.F33 J1.F36 J1.F39 J1.G1 J1.G4 J1.G5 J1.G8 J1.G11 J1.G14 J1.G17 J1.G20 J1.G23 J1.G26 J1.G29 J1.G32 J1.G35 J1.G38 J1.G40 J1.H3 J1.H6 J1.H9 J1.H12 J1.H15 J1.H18 J1.H21 J1.H24 J1.H27 J1.H30 J1.H33 J1.H36 J1.H39 J1.J1 J1.J4 J1.J5 J1.J8 J1.J11 J1.J14 J1.J17 J1.J20 J1.J23 J1.J26 J1.J29 J1.J32 J1.J35 J1.J38 J1.J40 J1.K2 J1.K3 J1.K6 J1.K9 J1.K12 J1.K15 J1.K30 J1.K33 J1.K36 J1.K39 J1.L7 J1.L30 J1.L31 J1.L34 J1.L35 J1.L38 J1.L39 J1.M1 J1.M29 J1.M32 J1.M33 J1.M36 J1.M37 J1.M40 J1.Y4 J1.Y5 J1.Y8 J1.Y9 J1.Y12 J1.Y13 J1.Y16 J1.Y17 J1.Y20 J1.Y21 J1.Y24 J1.Y25 J1.Y28 J1.Y29 J1.Y32 J1.Y33 J1.Y36 J1.Y37 J1.Y40 J1.Z2 J1.Z3 J1.Z7 J1.Z10 J1.Z11 J1.Z14 J1.Z15 J1.Z18 J1.Z19 J1.Z22 J1.Z23 J1.Z26 J1.Z27 J1.Z30 J1.Z31 J1.Z34 J1.Z35 J1.Z38 J1.Z39 J2.A1 J2.A4 J2.A5 J2.A8 J2.A9 J2.A12 J2.A13 J2.A16 J2.A17 J2.A20 J2.A21 J2.A24 J2.A25 J2.A28 J2.A29 J2.A32 J2.A33 J2.A36 J2.A37 J2.A40 J2.B3 J2.B6 J2.B7 J2.B10 J2.B11 J2.B14 J2.B15 J2.B18 J2.B19 J2.B22 J2.B23 J2.B26 J2.B27 J2.B30 J2.B31 J2.B34 J2.B35 J2.B38 J2.B39 J2.C1 J2.C4 J2.C5 J2.C8 J2.C9 J2.C12 J2.C13 J2.C16 J2.C17 J2.C20 J2.C21 J2.C24 J2.C25 J2.C28 J2.C29 J2.C32 J2.C33 J2.C36 J2.C38 J2.C40 J2.D2 J2.D3 J2.D6 J2.D7 J2.D10 J2.D13 J2.D16 J2.D19 J2.D25 J2.D28 J2.D37 J2.D39 J2.E1 J2.E4 J2.E5 J2.E8 J2.E11 J2.E14 J2.E17 J2.E23 J2.E26 J2.E29 J2.E32 J2.E35 J2.E38 J2.E40 J2.F3 J2.F6 J2.F9 J2.F12 J2.F15 J2.F18 J2.F21 J2.F24 J2.F27 J2.F30 J2.F33 J2.F36 J2.F39 J2.G1 J2.G4 J2.G5 J2.G8 J2.G11 J2.G14 J2.G17 J2.G20 J2.G23 J2.G26 J2.G29 J2.G32 J2.G35 J2.G38 J2.G40 J2.H3 J2.H6 J2.H9 J2.H12 J2.H15 J2.H18 J2.H21 J2.H24 J2.H27 J2.H30 J2.H33 J2.H36 J2.H39 J2.J1 J2.J4 J2.J5 J2.J8 J2.J11 J2.J14 J2.J17 J2.J20 J2.J23 J2.J26 J2.J29 J2.J32 J2.J35 J2.J38 J2.J40 J2.K2 J2.K3 J2.K6 J2.K9 J2.K12 J2.K15 J2.K30 J2.K33 J2.K36 J2.K39 J3.3 J3.5 J3.6 J3.8 J3.11 J3.13 J3.14 J3.16 J3.19 J3.21 J3.22 J3.24 J3.27 J3.29 J3.30 J3.32 J3.35 J3.37 J3.38 J3.40 J3.43 J3.45 J3.46 J3.48 J3.51 J3.53 J3.54 J3.56 J3.59 J3.MP1 J3.MP2 J3.MP3 J3.MP4 J4.A1 J4.A4 J4.A5 J4.A8 J4.A9 J4.A12 J4.A13 J4.A16 J4.A17 J4.A20 J4.A21 J4.A24 J4.A25 J4.A28 J4.A29 J4.A32 J4.A33 J4.A36 J4.A37 J4.A40 J4.B3 J4.B6 J4.B7 J4.B10 J4.B11 J4.B14 J4.B15 J4.B18 J4.B19 J4.B22 J4.B23 J4.B26 J4.B27 J4.B30 J4.B31 J4.B34 J4.B35 J4.B38 J4.B39 J4.C1 J4.C4 J4.C5 J4.C8 J4.C9 J4.C12 J4.C13 J4.C16 J4.C17 J4.C20 J4.C21 J4.C24 J4.C25 J4.C28 J4.C29 J4.C32 J4.C33 J4.C36 J4.C38 J4.C40 J4.D2 J4.D3 J4.D6 J4.D7 J4.D10 J4.D13 J4.D16 J4.D19 J4.D25 J4.D28 J4.D37 J4.D39 J4.E1 J4.E4 J4.E5 J4.E8 J4.E11 J4.E14 J4.E17 J4.E23 J4.E26 J4.E29 J4.E32 J4.E35 J4.E38 J4.E40 J4.F3 J4.F6 J4.F9 J4.F12 J4.F15 J4.F18 J4.F21 J4.F24 J4.F27 J4.F30 J4.F33 J4.F36 J4.F39 J4.G1 J4.G4 J4.G5 J4.G8 J4.G11 J4.G14 J4.G17 J4.G20 J4.G23 J4.G26 J4.G29 J4.G32 J4.G35 J4.G38 J4.G40 J4.H3 J4.H6 J4.H9 J4.H12 J4.H15 J4.H18 J4.H21 J4.H24 J4.H27 J4.H30 J4.H33 J4.H36 J4.H39 J4.J1 J4.J4 J4.J5 J4.J8 J4.J11 J4.J14 J4.J17 J4.J20 J4.J23 J4.J26 J4.J29 J4.J32 J4.J35 J4.J38 J4.J40 J4.K2 J4.K3 J4.K6 J4.K9 J4.K12 J4.K15 J4.K30 J4.K33 J4.K36 J4.K39 J4.L7 J4.L30 J4.L31 J4.L34 J4.L35 J4.L38 J4.L39 J4.M1 J4.M29 J4.M32 J4.M33 J4.M36 J4.M37 J4.M40 J4.Y4 J4.Y5 J4.Y8 J4.Y9 J4.Y12 J4.Y13 J4.Y16 J4.Y17 J4.Y20 J4.Y21 J4.Y24 J4.Y25 J4.Y28 J4.Y29 J4.Y32 J4.Y33 J4.Y36 J4.Y37 J4.Y40 J4.Z2 J4.Z3 J4.Z7 J4.Z10 J4.Z11 J4.Z14 J4.Z15 J4.Z18 J4.Z19 J4.Z22 J4.Z23 J4.Z26 J4.Z27 J4.Z30 J4.Z31 J4.Z34 J4.Z35 J4.Z38 J4.Z39 R45.1 R46.1 | length 2373.7
  L1_Top Layer w11: v1(535,1012.5) J1.B23@585,1062.5 J1.B22@585,1112.5 ; 1305.89,264.63 J3.59@1305.89,331.5 ; J3.56@1345.26,105.91 1345.26,175.71 ; J3.54@1364.95,105.91 1364.95,177.61 ; 1364.95,265.05 J3.53@1364.95,331.5 ; 1384.63,264.63 J3.51@1384.63,331.5 ; J3.48@1424,105.91 1424,175.71 ; J3.46@1443.69,105.91 1443.69,177.61 ; 1443.69,265.05 J3.45@1443.69,331.5 ; 1463.37,264.63 J3.43@1463.37,331.5 ; v1(1465,574) 1480.87,589.87 R45.1@1506,589.87 ; J3.40@1502.74,105.91 1502.74,175.71 ; J3.38@1522.43,105.91 1522.43,177.61 ; 1522.43,265.05 J3.37@1522.43,331.5 ; 1542.11,264.63 J3.35@1542.11,331.5 ; R46.1@1562,589.87 1585.13,589.87 v1(1600,575) ; J3.32@1581.48,105.91 1581.48,175.71 ; J3.30@1601.17,105.91 1601.17,177.61 ; 1601.17,265.05 J3.29@1601.17,331.5 ; 1620.86,264.63 J3.27@1620.86,331.5 ; J3.24@1660.23,105.91 1660.23,175.71 ; J3.22@1679.91,105.91 1679.91,177.61 ; 1679.91,265.05 J3.21@1679.91,331.5 ; 1699.6,264.63 J3.19@1699.6,331.5 ; J3.16@1738.97,105.91 1738.97,175.71 ; J3.14@1758.65,105.91 1758.65,177.61 ; 1758.65,265.05 J3.13@1758.65,331.5 ; 1778.34,264.63 J3.11@1778.34,331.5 ; J3.8@1817.71,105.91 1817.71,175.71 ; J3.6@1837.39,105.91 1837.39,177.61 ; 1837.39,265.05 J3.5@1837.39,331.5 ; 1857.08,264.63 J3.3@1857.08,331.5
  L1_Top Layer w20: J1.B7@585,1862.5 v1(585,1912.5)
  L12_Bottom Layer w11: v1(2608,1112.5) J2.A21@2658,1162.5 J2.A20@2658,1212.5
  other v1: 85,212.5 235,212.5 335,212.5 435,212.5 535,212.5 635,212.5 735,212.5 2108,212.5 2258,212.5 2358,212.5 2458,212.5 2558,212.5 2658,212.5 2758,212.5 1273.81,218.7 1409,219 1466.33,218.7 1528,219 1658,219 1778,219 1908.85,218.7 135,262.5 185,262.5 285,262.5 385,262.5 485,262.5 585,262.5 685,262.5 2158,262.5 2208,262.5 2308,262.5 2408,262.5 2508,262.5 2608,262.5 2708,262.5 135,312.5 235,312.5 335,312.5 435,312.5 535,312.5 585,312.5 685,312.5 2158,312.5 2258,312.5 2358,312.5 2458,312.5 2558,312.5 2608,312.5 2708,312.5 85,362.5 485,362.5 635,362.5 735,362.5 2108,362.5 2508,362.5 2658,362.5 2758,362.5 85,412.5 185,412.5 285,412.5 385,412.5 535,412.5 635,412.5 735,412.5 2108,412.5 2208,412.5 2308,412.5 2408,412.5 2558,412.5 2658,412.5 2758,412.5 135,462.5 235,462.5 335,462.5 435,462.5 585,462.5 685,462.5 2158,462.5 2258,462.5 2358,462.5 2458,462.5 2608,462.5 2708,462.5 135,512.5 585,512.5 685,512.5 2158,512.5 2608,512.5 2708,512.5 85,562.5 185,562.5 285,562.5 385,562.5 535,562.5 635,562.5 735,562.5 2108,562.5 2208,562.5 2308,562.5 2408,562.5 2558,562.5 2658,562.5 2758,562.5 85,612.5 235,612.5 335,612.5 435,612.5 535,612.5 635,612.5 735,612.5 2108,612.5 2258,612.5 2358,612.5 2458,612.5 2558,612.5 2658,612.5 2758,612.5 135,662.5 585,662.5 685,662.5 2158,662.5 2608,662.5 2708,662.5 135,712.5 185,712.5 285,712.5 385,712.5 585,712.5 685,712.5 2158,712.5 2208,712.5 2308,712.5 2408,712.5 2608,712.5 2708,712.5 85,762.5 235,762.5 335,762.5 435,762.5 535,762.5 635,762.5 735,762.5 2108,762.5 2258,762.5 2358,762.5 2458,762.5 2558,762.5 2658,762.5 2758,762.5 485,812.5 535,812.5 635,812.5 735,812.5 2508,812.5 2558,812.5 2658,812.5 2758,812.5 285,862.5 385,862.5 585,862.5 685,862.5 2308,862.5 2408,862.5 2608,862.5 2708,862.5 235,912.5 335,912.5 435,912.5 585,912.5 685,912.5 2258,912.5 2358,912.5 2458,912.5 2608,912.5 2708,912.5 485,962.5 535,962.5 635,962.5 735,962.5 2508,962.5 2558,962.5 2658,962.5 2758,962.5 285,1012.5 385,1012.5 635,1012.5 735,1012.5 2308,1012.5 2408,1012.5 2558,1012.5 2658,1012.5 2758,1012.5 235,1062.5 335,1062.5 435,1062.5 685,1062.5 2258,1062.5 2358,1062.5 2458,1062.5 2608,1062.5 2708,1062.5 685,1112.5 2708,1112.5 285,1162.5 385,1162.5 535,1162.5 635,1162.5 735,1162.5 2308,1162.5 2408,1162.5 2558,1162.5 2758,1162.5 235,1212.5 335,1212.5 535,1212.5 635,1212.5 735,1212.5 2258,1212.5 2358,1212.5 2558,1212.5 2758,1212.5 485,1262.5 585,1262.5 685,1262.5 2508,1262.5 2608,1262.5 2708,1262.5 285,1312.5 385,1312.5 585,1312.5 685,1312.5 2308,1312.5 2408,1312.5 2608,1312.5 2708,1312.5 235,1362.5 335,1362.5 435,1362.5 535,1362.5 635,1362.5 735,1362.5 2258,1362.5 2358,1362.5 2458,1362.5 2558,1362.5 2658,1362.5 2758,1362.5 485,1412.5 535,1412.5 635,1412.5 735,1412.5 2508,1412.5 2558,1412.5 2658,1412.5 2758,1412.5 185,1462.5 285,1462.5 385,1462.5 585,1462.5 685,1462.5 2208,1462.5 2308,1462.5 2408,1462.5 2608,1462.5 2708,1462.5 235,1512.5 335,1512.5 435,1512.5 585,1512.5 685,1512.5 2258,1512.5 2358,1512.5 2458,1512.5 2608,1512.5 2708,1512.5 485,1562.5 535,1562.5 635,1562.5 735,1562.5 2508,1562.5 2558,1562.5 2658,1562.5 2758,1562.5 185,1612.5 285,1612.5 385,1612.5 535,1612.5 635,1612.5 735,1612.5 2208,1612.5 2308,1612.5 2408,1612.5 2558,1612.5 2658,1612.5 2758,1612.5 235,1662.5 335,1662.5 435,1662.5 585,1662.5 685,1662.5 2258,1662.5 2358,1662.5 2458,1662.5 2608,1662.5 2708,1662.5 485,1712.5 585,1712.5 685,1712.5 2508,1712.5 2608,1712.5 2708,1712.5 185,1762.5 285,1762.5 385,1762.5 535,1762.5 635,1762.5 735,1762.5 2208,1762.5 2308,1762.5 2408,1762.5 2558,1762.5 2658,1762.5 2758,1762.5 235,1812.5 335,1812.5 435,1812.5 535,1812.5 635,1812.5 735,1812.5 2258,1812.5 2358,1812.5 2458,1812.5 2558,1812.5 2658,1812.5 2758,1812.5 135,1862.5 485,1862.5 685,1862.5 2158,1862.5 2508,1862.5 2608,1862.5 2708,1862.5 185,1912.5 285,1912.5 385,1912.5 485,1912.5 2208,1912.5 2308,1912.5 2408,1912.5 2508,1912.5 2608,1912.5 235,1962.5 335,1962.5 435,1962.5 535,1962.5 635,1962.5 735,1962.5 2258,1962.5 2358,1962.5 2458,1962.5 2558,1962.5 2658,1962.5 2758,1962.5 235,2012.5 335,2012.5 435,2012.5 535,2012.5 635,2012.5 735,2012.5 2258,2012.5 2358,2012.5 2458,2012.5 2558,2012.5 2658,2012.5 2758,2012.5 185,2062.5 285,2062.5 385,2062.5 485,2062.5 585,2062.5 685,2062.5 2208,2062.5 2308,2062.5 2408,2062.5 2508,2062.5 2608,2062.5 2708,2062.5 185,2112.5 485,2112.5 585,2112.5 685,2112.5 2208,2112.5 2508,2112.5 2708,2112.5 85,2162.5 235,2162.5 335,2162.5 435,2162.5 535,2162.5 635,2162.5 2108,2162.5 2258,2162.5 2358,2162.5 2458,2162.5 2558,2162.5 2658,2162.5
GPIO0: J1.H28 J2.H28 J4.H28 | length 2128.2
  L8_Signal Layer3 w4.25: v1(285,812.5) 315.5,843 965,843 1061.5,939.5 1838.5,939.5 1941.88,836.12 2284.38,836.12 v1(2308,812.5)
GPIO1: J1.H29 J2.H29 J4.H29 | length 2066.7
  L8_Signal Layer3 w4.25: v1(285,762.5) 314.5,733 481.28,733 534.03,785.75 2284.75,785.75 v1(2308,762.5)
H1: J1.H1 J2.H1 J4.H1 | length 2081.6
  L8_Signal Layer3 w4.25: v1(285,2162.5) 310.5,2137 402,2137 412,2147 412,2172 430,2190 2280.5,2190 v1(2308,2162.5)
H2: J1.H2 J2.H2 J4.H2 | length 2041.6
  L8_Signal Layer3 w4.25: v1(285,2112.5) 307.5,2090 2285.5,2090 v1(2308,2112.5)
H40: J1.H40 J2.H40 J4.H40 | length 2063.2
  L6_Signal Layer2 w3.75: v1(285,212.5) 333.5,164 v1(2115,164)
  L12_Bottom Layer w11: v1(2115,164) 2259.5,164 J2.H40@2308,212.5
J39: J1.J39 J2.J39 J4.J39 | length 2090.1
  L6_Signal Layer2 w3.75: v1(235,262.5) 259.5,238 759,238 815.5,181.5 2036.5,181.5 2092,237 2232.5,237 v1(2258,262.5)
K1: J1.K1 J2.K1 J4.K1 | length 2145.2
  L8_Signal Layer3 w4.25: v1(185,2162.5) 332.5,2310 1905,2310 v1(1955,2260)
  L12_Bottom Layer w11: v1(1955,2260) 1998,2217 2153.5,2217 J2.K1@2208,2162.5
K40: J1.K40 J2.K40 J4.K40 | length 2054.5
  L8_Signal Layer3 w4.25: v1(185,212.5) 202.5,230 544,230 582,192 2187.5,192 v1(2208,212.5)
LMK04828_RESET/FMC_FSPIDD: J2.J16 J4.J16 R38.2 R40.1 | length 1772.4
  L1_Top Layer w11: R40.1@1299,503.48 1325.48,503.48 v1(1337,515)
  L6_Signal Layer2 w3.75: v1(1337,515) 1380,472 1795,472 1945,622 1945,1307 2050.5,1412.5 v1(2258,1412.5)
LMK04828_SYNC/FMC_FSPIDC: J2.J15 J4.J15 R7.2 R8.1 | length 1684.1
  L1_Top Layer w11: R7.2@1379,503 1406,503 v1(1418,515)
  L6_Signal Layer2 w3.75: v1(1418,515) 1455,552 1850,552 1933,635 1933,1331 2038,1436 2231.5,1436 v1(2258,1462.5)
NB7_RESET: J1.H19 J2.H19 J4.H19 | length 2054.9
  L8_Signal Layer3 w4.25: v1(285,1262.5) 305,1242.5 758.5,1242.5 780,1264 2228,1264 2245,1281 2289.5,1281 v1(2308,1262.5)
